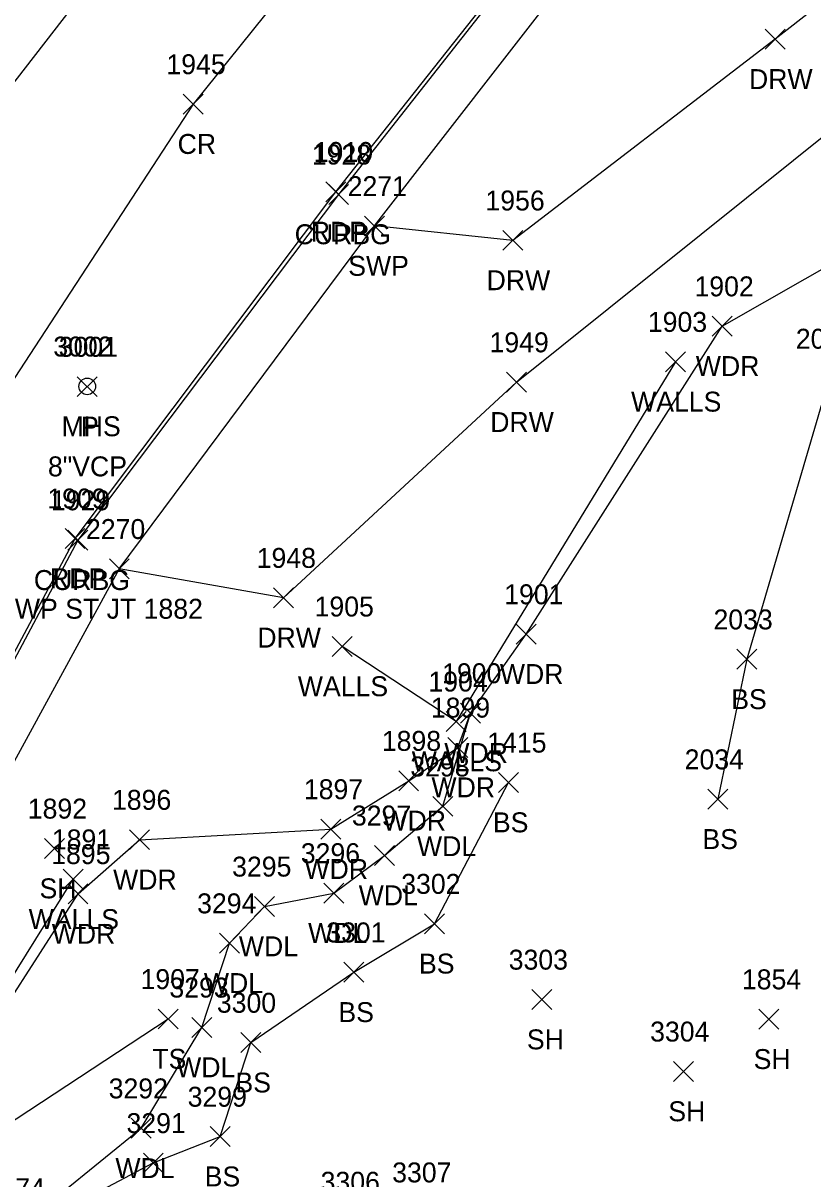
# Model space of a CAD drawing. Extents: x 462930 to 463548, y 29607 to 30453.
# Drawn here: x 463362.64 to 463386.81, y 30140.5 to 30175.85 of the extents above; entities that cross this region are included whole.
import ezdxf

# ---------------------------------------------------------------- set-up
doc = ezdxf.new("R2010")
doc.units = 0
for name, color, linetype in [('D_A', 7, 'Continuous'), ('D_C', 7, 'Continuous'), ('D_I', 7, 'Continuous'), ('D_TIC', 7, 'Continuous'), ('L_A', 7, 'Continuous'), ('L_I', 7, 'Continuous'), ('L_TIC', 7, 'Continuous'), ('LAWA', 7, 'Continuous'), ('LELB', 7, 'Continuous'), ('LWS', 7, 'Continuous'), ('P_A', 7, 'Continuous'), ('P_I', 7, 'Continuous'), ('P_TIC', 7, 'Continuous'), ('PET', 7, 'Continuous'), ('PRC', 7, 'Continuous'), ('R_A', 7, 'Continuous'), ('R_I', 7, 'Continuous'), ('R_TIC', 7, 'Continuous'), ('RC', 7, 'Continuous'), ('RDW', 7, 'Continuous'), ('RSW', 7, 'Continuous'), ('U_A', 7, 'Continuous'), ('U_I', 7, 'Continuous'), ('USMH', 7, 'Continuous')]:
    doc.layers.add(name, color=color, linetype=linetype)

msp = doc.modelspace()

# ---------------------------------------------------------------- linework, layer by layer
at = {"layer": 'D_TIC'}
for points in [[(463364.295, 30164.424), (463364.905, 30165.034)], [(463364.905, 30164.424), (463364.295, 30165.034)]]:
    msp.add_lwpolyline(points, dxfattribs=at)
at = {"layer": 'L_TIC'}
for points in [[(463383.725, 30166.272), (463384.335, 30166.882)], [(463384.335, 30166.272), (463383.725, 30166.882)], [(463382.298, 30165.185), (463382.908, 30165.795)], [(463382.908, 30165.185), (463382.298, 30165.795)], [(463377.729, 30156.855), (463378.339, 30157.465)], [(463378.339, 30156.855), (463377.729, 30157.465)], [(463372.101, 30156.481), (463372.711, 30157.091)], [(463372.711, 30156.481), (463372.101, 30157.091)], [(463384.48, 30156.086), (463385.09, 30156.696)], [(463385.09, 30156.086), (463384.48, 30156.696)], [(463376.029, 30154.44), (463376.639, 30155.05)], [(463376.639, 30154.44), (463376.029, 30155.05)], [(463375.585, 30154.186), (463376.195, 30154.796)], [(463376.195, 30154.186), (463375.585, 30154.796)], [(463375.636, 30153.389), (463376.246, 30153.999)], [(463376.246, 30153.389), (463375.636, 30153.999)], [(463374.135, 30152.372), (463374.745, 30152.982)], [(463374.745, 30152.372), (463374.135, 30152.982)], [(463377.187, 30152.319), (463377.797, 30152.929)], [(463377.797, 30152.319), (463377.187, 30152.929)], [(463383.598, 30151.807), (463384.208, 30152.417)], [(463384.208, 30151.807), (463383.598, 30152.417)], [(463375.177, 30151.59), (463375.787, 30152.2)], [(463375.787, 30151.59), (463375.177, 30152.2)], [(463371.749, 30150.893), (463372.359, 30151.503)], [(463372.359, 30150.893), (463371.749, 30151.503)], [(463365.895, 30150.569), (463366.505, 30151.179)], [(463366.505, 30150.569), (463365.895, 30151.179)], [(463363.301, 30150.3), (463363.911, 30150.91)], [(463363.911, 30150.3), (463363.301, 30150.91)], [(463373.392, 30150.088), (463374.002, 30150.698)], [(463374.002, 30150.088), (463373.392, 30150.698)], [(463363.865, 30149.359), (463364.475, 30149.969)], [(463364.475, 30149.359), (463363.865, 30149.969)], [(463364.017, 30148.909), (463364.627, 30149.519)], [(463364.627, 30148.909), (463364.017, 30149.519)], [(463371.845, 30148.937), (463372.454, 30149.547)], [(463372.454, 30148.937), (463371.845, 30149.547)], [(463369.727, 30148.527), (463370.336, 30149.137)], [(463370.336, 30148.527), (463369.727, 30149.137)], [(463374.925, 30147.999), (463375.535, 30148.608)], [(463375.535, 30147.999), (463374.925, 30148.608)], [(463368.656, 30147.403), (463369.265, 30148.013)], [(463369.265, 30147.403), (463368.656, 30148.013)], [(463372.459, 30146.515), (463373.069, 30147.125)], [(463373.069, 30146.515), (463372.459, 30147.125)], [(463378.213, 30145.681), (463378.823, 30146.291)], [(463378.823, 30145.681), (463378.213, 30146.291)], [(463366.775, 30145.086), (463367.385, 30145.696)], [(463367.385, 30145.086), (463366.775, 30145.696)], [(463385.152, 30145.079), (463385.762, 30145.689)], [(463385.762, 30145.079), (463385.152, 30145.689)], [(463367.807, 30144.827), (463368.417, 30145.436)], [(463368.417, 30144.827), (463367.807, 30145.436)], [(463369.309, 30144.363), (463369.919, 30144.973)], [(463369.919, 30144.363), (463369.309, 30144.973)], [(463382.541, 30143.482), (463383.151, 30144.091)], [(463383.151, 30143.482), (463382.541, 30144.091)], [(463365.949, 30141.744), (463366.558, 30142.353)], [(463366.558, 30141.744), (463365.949, 30142.353)], [(463368.368, 30141.489), (463368.978, 30142.098)], [(463368.978, 30141.489), (463368.368, 30142.098)], [(463366.322, 30140.682), (463366.931, 30141.292)], [(463366.931, 30140.682), (463366.322, 30141.292)]]:
    msp.add_lwpolyline(points, dxfattribs=at)
at = {"layer": 'LAWA'}
for points in [[(463359.706, 30142.039), (463364.322, 30149.214), (463366.2, 30150.874), (463372.054, 30151.198), (463374.44, 30152.677), (463375.941, 30153.694), (463376.334, 30154.745), (463378.034, 30157.16), (463384.03, 30166.577), (463387.88, 30168.775), (463397.819, 30177.75)], [(463375.482, 30151.895), (463376.334, 30154.745)], [(463361.075, 30139.951), (463362.489, 30138.995), (463366.254, 30142.049), (463368.112, 30145.132), (463368.96, 30147.708), (463370.031, 30148.832), (463372.15, 30149.242), (463373.697, 30150.393), (463375.482, 30151.895)]]:
    msp.add_lwpolyline(points, dxfattribs=at)
at = {"layer": 'LELB'}
for points in [[(463421.6, 30182.858), (463413.289, 30173.026), (463407.678, 30171.347), (463399.369, 30168.562), (463394.168, 30167.856), (463387.304, 30164.976), (463384.785, 30156.391), (463383.903, 30152.112)], [(463362.657, 30138.888), (463366.626, 30140.987), (463368.673, 30141.794), (463369.614, 30144.668), (463372.764, 30146.82), (463375.23, 30148.304), (463377.492, 30152.624)], [(463361.643, 30141.831), (463367.08, 30145.391)]]:
    msp.add_lwpolyline(points, dxfattribs=at)
at = {"layer": 'LWS'}
for points in [[(463382.603, 30165.49), (463375.89, 30154.491), (463372.406, 30156.786)], [(463360.634, 30145.247), (463359.088, 30142.671), (463359.593, 30142.33), (463364.17, 30149.664)]]:
    msp.add_lwpolyline(points, dxfattribs=at)
at = {"layer": 'P_TIC'}
for points in [[(463367.543, 30173.066), (463368.153, 30173.676)], [(463368.153, 30173.066), (463367.543, 30173.676)], [(463371.906, 30170.382), (463372.516, 30170.992)], [(463372.516, 30170.382), (463371.906, 30170.992)], [(463363.925, 30159.784), (463364.535, 30160.394)], [(463364.535, 30159.784), (463363.925, 30160.394)]]:
    msp.add_lwpolyline(points, dxfattribs=at)
at = {"layer": 'PET'}
for points in [[(463357.128, 30146.779), (463364.23, 30160.089), (463372.211, 30170.687), (463380.439, 30181.089), (463388.986, 30192.495), (463395.438, 30204.072), (463399.65, 30216.413), (463402.389, 30229.411), (463403.525, 30242.02), (463404.007, 30246.74), (463403.926, 30248.538), (463404.123, 30251.434)], [(463357.576, 30167.469), (463361.27, 30172.626), (463368.225, 30181.594), (463376.26, 30192.198)]]:
    msp.add_lwpolyline(points, dxfattribs=at)
at = {"layer": 'PRC'}
msp.add_lwpolyline([(463399.789, 30246.987), (463397.991, 30230.027), (463395.304, 30217.172), (463391.095, 30206.312), (463384.492, 30195.113), (463376.573, 30184.227), (463367.848, 30173.371), (463360.659, 30162.372), (463353.283, 30149.309)], dxfattribs=at)
at = {"layer": 'R_TIC'}
for points in [[(463385.35, 30175.049), (463385.96, 30175.659)], [(463385.96, 30175.049), (463385.35, 30175.659)], [(463371.992, 30170.304), (463372.602, 30170.914)], [(463372.602, 30170.304), (463371.992, 30170.914)], [(463373.089, 30169.338), (463373.699, 30169.948)], [(463373.699, 30169.338), (463373.089, 30169.948)], [(463377.322, 30168.899), (463377.932, 30169.509)], [(463377.932, 30168.899), (463377.322, 30169.509)], [(463377.432, 30164.561), (463378.042, 30165.171)], [(463378.042, 30164.561), (463377.432, 30165.171)], [(463364.011, 30159.729), (463364.621, 30160.339)], [(463364.621, 30159.729), (463364.011, 30160.339)], [(463365.281, 30158.851), (463365.891, 30159.461)], [(463365.891, 30158.851), (463365.281, 30159.461)], [(463370.306, 30157.968), (463370.916, 30158.578)], [(463370.916, 30157.968), (463370.306, 30158.578)]]:
    msp.add_lwpolyline(points, dxfattribs=at)
at = {"layer": 'RC'}
msp.add_lwpolyline([(463403.888, 30243.164), (463403.731, 30243.164), (463403.598, 30241.759), (463402.492, 30229.375), (463399.74, 30216.359), (463395.506, 30204.018), (463389.016, 30192.435), (463380.487, 30181.016), (463372.297, 30170.609), (463364.316, 30160.034), (463357.246, 30146.767)], dxfattribs=at)
at = {"layer": 'RDW'}
for points in [[(463370.611, 30158.273), (463377.737, 30164.866), (463387.605, 30172.767), (463398.297, 30179.61), (463406.605, 30184.823), (463404.673, 30188.349), (463395.336, 30182.896), (463385.655, 30175.354), (463377.627, 30169.204)], [(463377.627, 30169.204), (463373.394, 30169.643)], [(463370.611, 30158.273), (463365.586, 30159.156)]]:
    msp.add_lwpolyline(points, dxfattribs=at)
at = {"layer": 'RSW'}
for points in [[(463365.586, 30159.156), (463373.394, 30169.643), (463381.656, 30180.281), (463390.273, 30191.668), (463396.887, 30203.599), (463401.229, 30215.977), (463404.093, 30229.321), (463404.817, 30241.819)], [(463365.586, 30159.156), (463359.511, 30148.043)]]:
    msp.add_lwpolyline(points, dxfattribs=at)
at = {"layer": 'USMH'}
for p, q in [((463364.606, 30164.737), (463364.606, 30164.737)), ((463364.86, 30164.737), (463364.86, 30164.737))]:
    msp.add_line(p, q, dxfattribs=at)
msp.add_circle((463364.606, 30164.737), 0.254, dxfattribs=at)

# ---------------------------------------------------------------- texts
at = {"layer": 'D_A'}
msp.add_text('P', height=0.61, dxfattribs=at).set_placement((463364.41, 30163.205))
at = {"layer": 'D_C'}
msp.add_text('8"VCP', height=0.6096, dxfattribs=at).set_placement((463363.402, 30161.986))
at = {"layer": 'D_I'}
msp.add_text('3001', height=0.6096, dxfattribs=at).set_placement((463363.731, 30165.643))
at = {"layer": 'L_A'}
for s, p in [('WDR', (463383.226, 30165.053)), ('WALLS', (463381.245, 30163.966)), ('WDR', (463377.23, 30155.636)), ('WALLS', (463371.048, 30155.262)), ('BS', (463384.31, 30154.867)), ('WDR', (463375.53, 30153.221)), ('WALLS', (463374.532, 30152.967)), ('WDR', (463375.137, 30152.17)), ('WDR', (463373.636, 30151.153)), ('BS', (463377.017, 30151.1)), ('WDL', (463374.695, 30150.371)), ('BS', (463383.428, 30150.588)), ('WDR', (463371.25, 30149.674)), ('WDR', (463365.396, 30149.35)), ('SH', (463363.145, 30149.081)), ('WDL', (463372.91, 30148.869)), ('WALLS', (463362.812, 30148.14)), ('WDR', (463363.518, 30147.69)), ('WDL', (463371.362, 30147.718)), ('WDL', (463369.244, 30147.308)), ('BS', (463374.755, 30146.78)), ('WDL', (463368.173, 30146.184)), ('BS', (463372.289, 30145.296)), ('SH', (463378.057, 30144.462)), ('TS', (463366.595, 30143.867)), ('WDL', (463367.325, 30143.608)), ('SH', (463384.996, 30143.86)), ('BS', (463369.139, 30143.144)), ('SH', (463382.385, 30142.263)), ('WDL', (463365.466, 30140.525)), ('BS', (463368.198, 30140.27))]:
    msp.add_text(s, height=0.6096, dxfattribs=at).set_placement(p)
at = {"layer": 'L_I'}
for s, p in [('1902', (463383.185, 30167.491)), ('1903', (463381.758, 30166.404)), ('2032', (463386.286, 30165.89)), ('1901', (463377.362, 30158.074)), ('1905', (463371.561, 30157.7)), ('2033', (463383.767, 30157.305)), ('1900', (463375.463, 30155.659)), ('1904', (463375.045, 30155.405)), ('1899', (463375.118, 30154.608)), ('1898', (463373.619, 30153.591)), ('1415', (463376.844, 30153.538)), ('3298', (463374.489, 30152.809)), ('2034', (463382.885, 30153.026)), ('1897', (463371.233, 30152.112)), ('1896', (463365.362, 30151.788)), ('1892', (463362.785, 30151.519)), ('3297', (463372.703, 30151.308)), ('1891', (463363.522, 30150.578)), ('1895', (463363.501, 30150.128)), ('3296', (463371.139, 30150.156)), ('3295', (463369.038, 30149.746)), ('3302', (463374.212, 30149.218)), ('3294', (463367.967, 30148.622)), ('3301', (463371.919, 30147.734)), ('3303', (463377.501, 30146.9)), ('1907', (463366.235, 30146.305)), ('1854', (463384.636, 30146.298)), ('3293', (463367.118, 30146.046)), ('3300', (463368.57, 30145.582)), ('3304', (463381.828, 30144.701)), ('3292', (463365.26, 30142.963)), ('3299', (463367.677, 30142.708)), ('3291', (463365.806, 30141.901)), ('3306', (463371.746, 30140.107)), ('3307', (463373.935, 30140.393)), ('3274', (463361.496, 30139.909)), ('3274', (463361.496, 30139.909))]:
    msp.add_text(s, height=0.6096, dxfattribs=at).set_placement(p)
at = {"layer": 'P_A'}
for s, p in [('CR', (463367.37, 30171.847)), ('RDP', (463371.445, 30169.163)), ('RDP', (463363.464, 30158.565))]:
    msp.add_text(s, height=0.6096, dxfattribs=at).set_placement(p)
at = {"layer": 'P_I'}
for s, p in [('1945', (463367.027, 30174.285)), ('1910', (463371.537, 30171.601)), ('1909', (463363.383, 30161.003))]:
    msp.add_text(s, height=0.6096, dxfattribs=at).set_placement(p)
at = {"layer": 'R_A'}
for s, p in [('DRW', (463384.853, 30173.83)), ('CURBG', (463370.951, 30169.085)), ('SWP', (463372.59, 30168.119)), ('DRW', (463376.825, 30167.68)), ('DRW', (463376.935, 30163.342)), ('CURBG', (463362.97, 30158.51)), ('SWP ST JT 1882', (463361.847, 30157.632)), ('DRW', (463369.809, 30156.749))]:
    msp.add_text(s, height=0.6096, dxfattribs=at).set_placement(p)
at = {"layer": 'R_I'}
for s, p in [('1928', (463371.476, 30171.523)), ('2271', (463372.573, 30170.557)), ('1956', (463376.789, 30170.118)), ('1949', (463376.914, 30165.78)), ('1929', (463363.493, 30160.948)), ('2270', (463364.566, 30160.07)), ('1948', (463369.79, 30159.187))]:
    msp.add_text(s, height=0.6096, dxfattribs=at).set_placement(p)
at = {"layer": 'U_A'}
msp.add_text('MHS', height=0.6096, dxfattribs=at).set_placement((463363.819, 30163.213))
at = {"layer": 'U_I'}
msp.add_text('3002', height=0.6096, dxfattribs=at).set_placement((463363.565, 30165.651))

doc.saveas('drawing.dxf')
